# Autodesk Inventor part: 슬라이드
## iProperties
Company: 한국ATC센터
Created: 2014-10
Part Number: 슬라이드
Document SubType Name: Modeling
Designer: 한국ATC센터
Density: 7.86 g/cm^3
Material: 강, 연강
Mass: 702.202 g
Surface Area: 150.69 cm^2
Volume: 89.3387 cm^3
Author: KYOUNG IL JANG
Revision Number: 1
